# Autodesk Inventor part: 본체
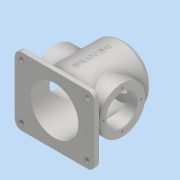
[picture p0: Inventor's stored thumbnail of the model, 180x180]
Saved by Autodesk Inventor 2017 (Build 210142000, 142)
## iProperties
Part Number: 본체
Material: 알루미늄 6061
Document SubType Name: Modeling
Designer: MRC
Density: 2.7 g/cm^3
Appearance: 알루미늄 - 평지
Mass: 1235.53 g
Surface Area: 1067.6 cm^2
Volume: 457.603 cm^3
Author: MRC
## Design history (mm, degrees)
sketch "스케치1"
  geometry: C1 r 50 at (0, 0); 1 further point
  constraints: 1 centre point, 1 coincident
  dimensions: "d0" = 100 diameter of C1
extrude "돌출1" new body sketch "스케치1" stored distance "d1" = 120; taper "d2" = 0 deg
sketch "스케치2"
  geometry: L1 (70, -60)-(-70, -60); L2 (-70, -60)-(-70, 60); L3 (-70, 60)-(70, 60); L4 (70, 60)-(70, -60); L5 (70, -60)-(-70, 60); L6 (-70, -60)-(70, 60); C1 r 50 at (0, 0); 1 further point
  constraints: 12 end point, 2 midpoint, 2 parallel, 1 centre point, 1 coincident, 1 horizontal, 1 perpendicular
  dimensions: "d3" = 140 distance of L2.end L3.end; "d4" = 120 distance of L1.end L2.end; "d14" = 100 diameter of C1
sketch "스케치3"
  geometry: C1 r 41 at (0, 0); 1 further point
  constraints: 1 centre point, 1 coincident
  dimensions: "d7" = 82 diameter of C1
extrude "돌출3" join sketch "스케치3" distance "d8" = 5; taper "d9" = 0 deg
node "작업 평면1"
sketch "스케치4"
  geometry: C1 r 41 at (0, 0); 1 further point
  constraints: 1 centre point, 1 coincident
  dimensions: "d11" = 82 diameter of C1
extrude "돌출4" join sketch "스케치4" stored distance "d12" = 5; taper "d13" = 0 deg
extrude "돌출5" join sketch "스케치2" distance "d15" = 10; taper "d16" = 0 deg
sketch "스케치5"
  geometry: 2 further points
  constraints: 1 coincident
hole "구멍1" sketch "스케치5" at (0, 0) diameter "d17" = 54; stored, may be unused: countersink angle "d21" = 90 deg, drill point angle "d23" = 118 deg; dims "d18" = 6, "d19" = 84, "d20" = 112, "d22" = 8
sketch "스케치6"
  geometry: C1 r 27 at (0, 0); 1 further point
  constraints: 1 centre point, 1 coincident
  dimensions: "d24" = 54 diameter of C1
extrude "돌출6" cut sketch "스케치6" stored distance "d25" = 10; taper "d26" = 0 deg
sketch "스케치7"
  geometry: 2 further points
  constraints: 1 vertical alignment
  dimensions: "d27" = 33 distance of point (0, 0) point (0, 33)
hole "구멍2" sketch "스케치7" at (0, 33) diameter "d28" = 3.242; stored, may be unused: countersink angle "d32" = 90 deg, drill point angle "d34" = 118 deg; dims "d29" = 8, "d30" = 84, "d31" = 112, "d33" = 10
chamfer "모따기1" distance "d38" = 1; stored, may be unused: second distance "d39" = 2, angle "d40" = 45 deg
chamfer "모따기2" distance "d41" = 1; stored, may be unused: second distance "d42" = 2, angle "d43" = 45 deg
sketch "스케치8"
  geometry: 2 further points
  constraints: 1 vertical alignment
  dimensions: "d44" = 33 distance of point (0, 0) point (0, 33)
hole "구멍3" sketch "스케치8" at (0, 33) diameter "d45" = 3.242; stored, may be unused: countersink angle "d49" = 90 deg, drill point angle "d51" = 118 deg; dims "d46" = 8, "d47" = 84, "d48" = 112, "d50" = 10
fillet "모깎기1" dims "d55" = 12, "d62" = 6
sketch "스케치9"
  geometry: C1 r 4.5 at (-58, 48); C2 r 4.5 at (58, 48); C3 r 4.5 at (58, -48); C4 r 4.5 at (-58, -48); A1 r 12 centre (-58, 48) between (-58, 60) and (-70, 48) reference; A2 r 12 centre (58, 48) between (70, 48) and (58, 60) reference; A3 r 12 centre (58, -48) between (58, -60) and (70, -48) reference; A4 r 12 centre (-58, -48) between (-70, -48) and (-58, -60) reference; 1 further point
  constraints: 4 centre point, 4 coincident
  dimensions: "d56" = 9 diameter of C1; "d57" = 9 diameter of C2; "d58" = 9 diameter of C3; "d59" = 9 diameter of C4
extrude "돌출7" cut sketch "스케치9" stored distance "d60" = 10; taper "d61" = 0 deg
fillet "모깎기2" dims "d63" = 3
node "작업 평면2"
sketch "스케치10"
  geometry: L1 (-58, -60)-(58, -60) reference; 2 further points
  constraints: 1 vertical alignment, 1 other
  dimensions: "d64" = 66 distance from line of point (0, 6) L1
feature "엠보싱1" sketch "스케치10" dims "d65" = 0.5, "d66" = 0
node "솔리드1"
pattern_circular "원형 패턴1" dims angle "d36" = 360 deg
mirror "미러1"
pattern_circular "원형 패턴2" dims angle "d53" = 360 deg
other parameters: "d10" = 59
